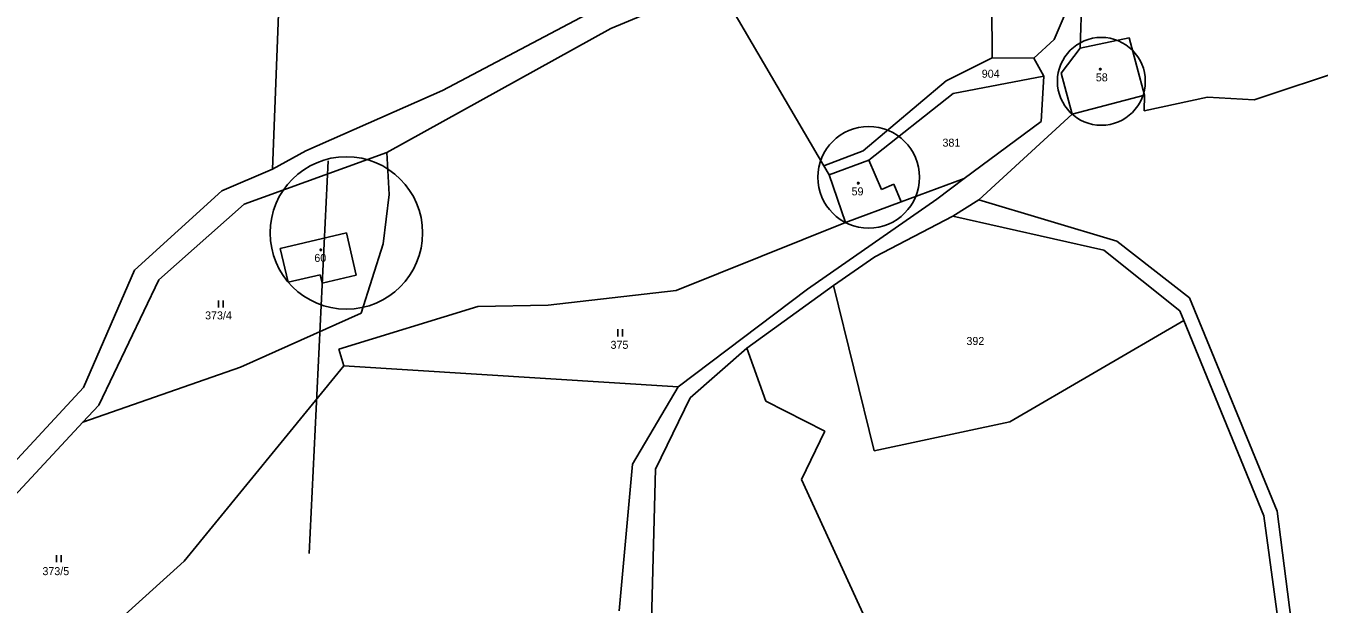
# Model space of a CAD drawing. Extents: x -580551 to -575069, y -1073031 to -1067931.
# Drawn here: x -577343.9 to -577069.2, y -1070091.5 to -1069968.7 of the extents above; entities that cross this region are included whole.
import ezdxf

# ---------------------------------------------------------------- set-up
doc = ezdxf.new("R2010")
doc.units = 0
for name, color, linetype in [('Druh pozemku', 7, 'Continuous'), ('Parcela', 7, 'Continuous'), ('Parcelní číslo', 7, 'Continuous'), ('Parcelní číslo_stavba', 7, 'Continuous'), ('SR - hranice státu', 7, 'Continuous'), ('stavební parcely', 7, 'Continuous'), ('Vrstva 6', 7, 'Continuous')]:
    doc.layers.add(name, color=color, linetype=linetype)

msp = doc.modelspace()

# ---------------------------------------------------------------- linework, layer by layer
at = {"layer": 'Druh pozemku'}
for p, q in [((-577302.99, -1070027.01), (-577302.99, -1070028.51)), ((-577301.99, -1070028.51), (-577301.99, -1070027.01)), ((-577218.16, -1070033.16), (-577218.16, -1070034.66)), ((-577217.16, -1070034.66), (-577217.16, -1070033.16)), ((-577337.37, -1070081.14), (-577337.37, -1070082.64)), ((-577336.37, -1070082.64), (-577336.37, -1070081.14))]:
    msp.add_line(p, q, dxfattribs=at)
for points in [[(-577115.6, -1069977.76), (-577115.51, -1069977.91), (-577115.6, -1069978.06), (-577115.78, -1069978.06), (-577115.87, -1069977.91), (-577115.78, -1069977.76)], [(-577167, -1070001.97), (-577166.91, -1070002.12), (-577167, -1070002.27), (-577167.18, -1070002.27), (-577167.27, -1070002.12), (-577167.18, -1070001.97)], [(-577281.13, -1070016.13), (-577281.04, -1070016.28), (-577281.13, -1070016.43), (-577281.31, -1070016.43), (-577281.4, -1070016.28), (-577281.31, -1070016.13)]]:
    msp.add_lwpolyline(points, close=True, dxfattribs=at)
at = {"layer": 'Parcela'}
for p, q in [((-577288.66, -1069925.7), (-577291.47, -1069999.12)), ((-577119.95, -1069973.43), (-577119.29, -1069952.63)), ((-577197.02, -1069959.85), (-577219.63, -1069969.3)), ((-577174.37, -1069998.46), (-577197.02, -1069959.85)), ((-577138.74, -1069964.25), (-577138.66, -1069975.52)), ((-577125.46, -1069971.6), (-577122.48, -1069964.7)), ((-577255.36, -1069982.47), (-577227.38, -1069967.65)), ((-577219.63, -1069969.3), (-577267.24, -1069995.63)), ((-577129.82, -1069975.55), (-577125.46, -1069971.6)), ((-577124, -1069978.79), (-577119.95, -1069973.43)), ((-577119.95, -1069973.43), (-577109.52, -1069971.26)), ((-577109.52, -1069971.26), (-577106.29, -1069983.43)), ((-577148.4, -1069980.36), (-577138.66, -1069975.52)), ((-577138.66, -1069975.52), (-577129.82, -1069975.55)), ((-577129.82, -1069975.55), (-577127.68, -1069979.38)), ((-577082.98, -1069984.46), (-577054.76, -1069975.04)), ((-577121.67, -1069987.47), (-577124, -1069978.79)), ((-577166.03, -1069995.27), (-577148.4, -1069980.36)), ((-577127.68, -1069979.38), (-577146.96, -1069983.08)), ((-577128.21, -1069989.06), (-577127.68, -1069979.38)), ((-577284.41, -1069995.28), (-577255.36, -1069982.47)), ((-577146.96, -1069983.08), (-577164.83, -1069997.23)), ((-577121.67, -1069987.47), (-577106.29, -1069983.43)), ((-577106.29, -1069983.43), (-577106.36, -1069986.78)), ((-577106.36, -1069986.78), (-577092.94, -1069983.84)), ((-577092.94, -1069983.84), (-577082.98, -1069984.46)), ((-577128.21, -1069989.06), (-577144.61, -1070001.15)), ((-577141.45, -1070005.67), (-577121.67, -1069987.47)), ((-577291.47, -1069999.12), (-577284.41, -1069995.28)), ((-577174.37, -1069998.46), (-577166.03, -1069995.27)), ((-577267.24, -1069995.63), (-577297.48, -1070006.55)), ((-577279.648, -1069997.36), (-577283.698, -1070080.81)), ((-577164.83, -1069997.23), (-577173.26, -1070000.35)), ((-577164.83, -1069997.23), (-577162.14, -1070003.45)), ((-577291.47, -1069999.12), (-577302.27, -1070003.74)), ((-577173.26, -1070000.35), (-577174.37, -1069998.46)), ((-577173.26, -1070000.35), (-577169.82, -1070010.48)), ((-577162.14, -1070003.45), (-577159.56, -1070002.33)), ((-577159.56, -1070002.33), (-577157.94, -1070006.08)), ((-577157.94, -1070006.08), (-577144.61, -1070001.15)), ((-577144.61, -1070001.15), (-577150.37, -1070005.53)), ((-577302.27, -1070003.74), (-577320.77, -1070020.63)), ((-577150.37, -1070005.53), (-577177.84, -1070024.63)), ((-577169.82, -1070010.48), (-577157.94, -1070006.08)), ((-577147, -1070009.13), (-577141.45, -1070005.67)), ((-577141.45, -1070005.67), (-577112.15, -1070014.44)), ((-577297.48, -1070006.55), (-577315.62, -1070022.64)), ((-577147, -1070009.13), (-577163.54, -1070017.79)), ((-577114.95, -1070016.34), (-577147, -1070009.13)), ((-577205.74, -1070024.9), (-577169.82, -1070010.48)), ((-577289.84, -1070015.99), (-577275.8, -1070012.7)), ((-577275.8, -1070012.7), (-577273.73, -1070021.67)), ((-577112.15, -1070014.44), (-577096.73, -1070026.49)), ((-577288.16, -1070023.16), (-577289.84, -1070015.99)), ((-577098.8, -1070029.22), (-577114.95, -1070016.34)), ((-577163.54, -1070017.79), (-577172.32, -1070023.83)), ((-577320.77, -1070020.63), (-577331.64, -1070045.5)), ((-577315.62, -1070022.64), (-577328.35, -1070049.24)), ((-577281.35, -1070021.57), (-577288.16, -1070023.16)), ((-577280.95, -1070023.34), (-577281.35, -1070021.57)), ((-577273.73, -1070021.67), (-577280.95, -1070023.34)), ((-577232.97, -1070028.02), (-577205.74, -1070024.9)), ((-577177.84, -1070024.63), (-577205.35, -1070045.41)), ((-577172.32, -1070023.83), (-577190.74, -1070037.18)), ((-577172.32, -1070023.83), (-577163.72, -1070058.95)), ((-577277.43, -1070037.4), (-577247.91, -1070028.31)), ((-577247.91, -1070028.31), (-577232.97, -1070028.02)), ((-577096.73, -1070026.49), (-577078.12, -1070071.77)), ((-577097.96, -1070031.26), (-577098.8, -1070029.22)), ((-577134.89, -1070052.81), (-577097.96, -1070031.26)), ((-577080.92, -1070072.77), (-577097.96, -1070031.26)), ((-577276.35, -1070040.89), (-577277.43, -1070037.4)), ((-577190.74, -1070037.18), (-577202.78, -1070047.7)), ((-577190.74, -1070037.18), (-577186.74, -1070048.45)), ((-577205.35, -1070045.41), (-577276.35, -1070040.89)), ((-577331.64, -1070045.5), (-577353.32, -1070068.95)), ((-577205.35, -1070045.41), (-577215.01, -1070061.78)), ((-577328.35, -1070049.24), (-577331.77, -1070052.91)), ((-577202.78, -1070047.7), (-577210.18, -1070062.88)), ((-577186.74, -1070048.45), (-577174.18, -1070054.78)), ((-577331.77, -1070052.91), (-577350.91, -1070073.5)), ((-577163.72, -1070058.95), (-577134.89, -1070052.81)), ((-577174.18, -1070054.78), (-577179.13, -1070065.09)), ((-577215.01, -1070061.78), (-577217.83, -1070092.94)), ((-577210.18, -1070062.88), (-577211.05, -1070098.17)), ((-577179.13, -1070065.09), (-577116.3, -1070201.69)), ((-577078.12, -1070071.77), (-577069.79, -1070136.39)), ((-577072.23, -1070137.82), (-577080.92, -1070072.77))]:
    msp.add_line(p, q, dxfattribs=at)
at = {"layer": 'SR - hranice státu'}
msp.add_line((-577288.66, -1069925.7), (-577291.47, -1069999.12), dxfattribs=at)
msp.add_lwpolyline([(-577291.47, -1069999.12), (-577284.41, -1069995.28), (-577255.36, -1069982.47), (-577227.38, -1069967.65), (-577223.71, -1069965.71)], dxfattribs=at)
at = {"layer": 'stavební parcely'}
for centre, radius in [((-577115.46, -1069980.5), 9.335), ((-577164.879, -1070000.878), 10.799), ((-577275.8, -1070012.7), 16.192)]:
    msp.add_circle(centre, radius, dxfattribs=at)
at = {"layer": 'Vrstva 6'}
for p, q in [((-577267.24, -1069995.63), (-577266.71, -1070004.54)), ((-577266.71, -1070004.54), (-577267.97, -1070015.02)), ((-577267.97, -1070015.02), (-577272.68, -1070029.75)), ((-577272.68, -1070029.75), (-577298.27, -1070041.23)), ((-577298.27, -1070041.23), (-577331.77, -1070052.91)), ((-577276.35, -1070040.89), (-577310.27, -1070082.4)), ((-577310.27, -1070082.4), (-577343.16, -1070112.14))]:
    msp.add_line(p, q, dxfattribs=at)

# ---------------------------------------------------------------- texts
at = {"layer": 'Parcelní číslo'}
for s, p in [('904', (-577140.858, -1069979.73)), ('381', (-577149.198, -1069994.37)), ('373/4', (-577305.807, -1070031.06)), ('375', (-577219.697, -1070037.31)), ('392', (-577144.116, -1070036.49)), ('373/5', (-577340.349, -1070085.38))]:
    msp.add_text(s, height=1.7, dxfattribs=at).set_placement(p)
at = {"layer": 'Parcelní číslo_stavba'}
for s, p in [('58', (-577116.635, -1069980.5)), ('59', (-577168.507, -1070004.72)), ('60', (-577282.6, -1070018.85))]:
    msp.add_text(s, height=1.7, dxfattribs=at).set_placement(p)

doc.saveas('drawing.dxf')
